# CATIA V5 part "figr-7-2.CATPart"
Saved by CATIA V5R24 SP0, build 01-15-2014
Part number: Part1
Bounding box of the stored display mesh (mm): x -50 to 50, y -75 to 75, z 0 to 10
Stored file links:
  D:\KAVITA\CATIA V5-6R2014 Project_ Kavita\CATIA V5-6R2014_partfiles\Partfiles\c07_catia_v5-6r2014_prt\figr-7-2.CATPart
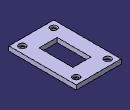
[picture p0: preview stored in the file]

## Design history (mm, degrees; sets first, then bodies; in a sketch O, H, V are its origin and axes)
Body1 (main body)
  Sketch1 on xy-plane, origin (0, 0, 0), H (1, 0, 0), V (0, 1, 0)
    line L1 (-50, 75) -> (50, 75)
    line L2 (50, 75) -> (50, -75)
    line L3 (50, -75) -> (-50, -75)
    line L4 (-50, -75) -> (-50, 75)
    axis line L5 (50, -75) -> (-50, 75)
    length L3 = 100
    length L2 = 150
    horizontal: L1 H, L3 H
    vertical: L2 V, L4 V
    midpoint: O L5
  Pad1: profile Sketch1, direction (0, 0, 1), length 10
  Sketch2 on face of Pad1, origin (0, 0, 10), H (1, 0, 0), V (0, 1, 0)
    line L1 (-20, 37.5) -> (20, 37.5)
    line L2 (20, 37.5) -> (20, -37.5)
    line L3 (20, -37.5) -> (-20, -37.5)
    line L4 (-20, -37.5) -> (-20, 37.5)
    axis line L5 (20, -37.5) -> (-20, 37.5)
    length L3 = 40
    length L2 = 75
    horizontal: L1 H, L3 H
    vertical: L2 V, L4 V
    midpoint: O L5
  Pocket1: profile Sketch2, direction (0, 0, -1), through (limit type 3)
  Sketch3 on face of Pad1, origin (-33.8832, 14.5619, 10), H (1, 0, 0), V (0, 1, 0)
    point P1 (68.8832, -74.5619)
    reference projected line E1 (-16.1168, -89.5619) -> (83.8832, -89.5619) from edge [face of Pad1 | face of Pad1]
    reference projected line E2 (83.8832, -89.5619) -> (83.8832, 60.4381) from edge [face of Pad1 | face of Pad1]
    distance P1 E1 = 15
    distance P1 E2 = 15
  Hole1: placed by Sketch3, at (35, -60, 10) direction (0, 0, -1), diameter 10, through (limit type 3), counterbore diameter 15, counterbore depth 5
  RectPattern1: of Hole1, direction 1 instances 2, spacing 70, along edge [face of Pad1 | face of Pad1] reversed, direction 2 instances 2, spacing 120, along edge [face of Pad1 | face of Pad1]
